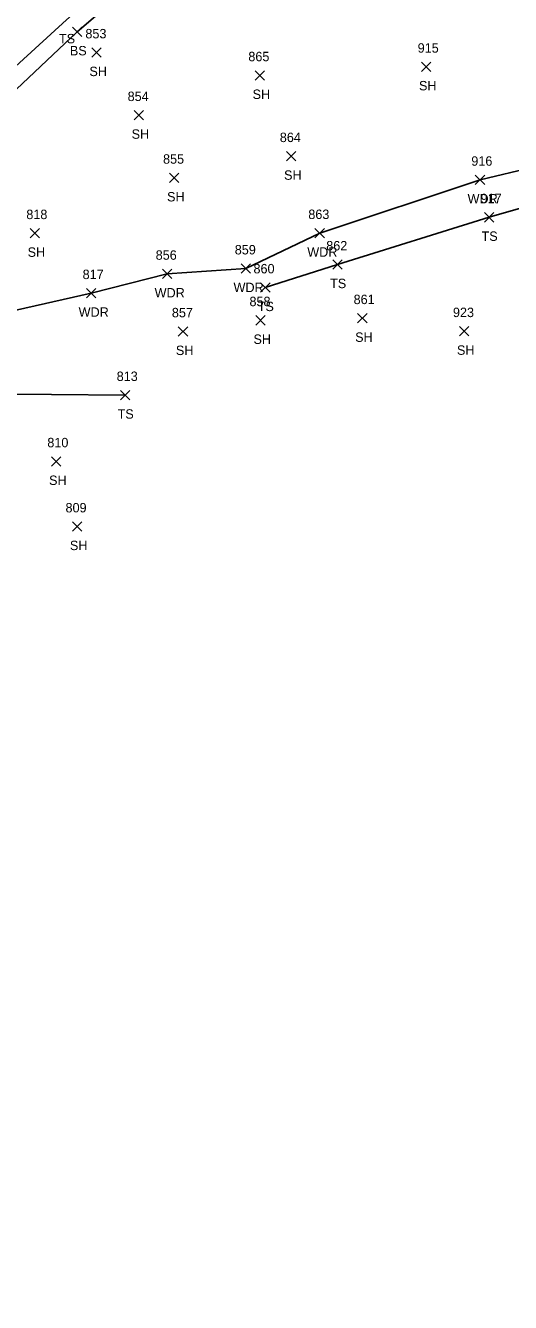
# Model space of a CAD drawing. Extents: x 1586965 to 1590952, y 716317 to 720029.
# Drawn here: x 1587304.9 to 1587407.7, y 719388.4 to 719659.2 of the extents above; entities that cross this region are included whole.
import ezdxf

# ---------------------------------------------------------------- set-up
doc = ezdxf.new("R2010")
doc.units = 0
for name, color, linetype in [('L_A', 7, 'Continuous'), ('L_I', 7, 'Continuous'), ('L_TIC', 7, 'Continuous'), ('LAWA', 7, 'Continuous'), ('LELB', 7, 'Continuous')]:
    doc.layers.add(name, color=color, linetype=linetype)

msp = doc.modelspace()

# ---------------------------------------------------------------- linework, layer by layer
at = {"layer": 'L_TIC'}
for points in [[(1587314.89, 719656.91), (1587316.89, 719658.91)], [(1587316.89, 719656.91), (1587314.89, 719658.91)], [(1587318.98, 719652.52), (1587320.98, 719654.52)], [(1587320.98, 719652.52), (1587318.98, 719654.52)], [(1587353.57, 719647.67), (1587355.57, 719649.67)], [(1587355.57, 719647.67), (1587353.57, 719649.67)], [(1587388.85, 719649.49), (1587390.85, 719651.49)], [(1587390.85, 719649.49), (1587388.85, 719651.49)], [(1587327.93, 719639.23), (1587329.93, 719641.23)], [(1587329.93, 719639.23), (1587327.93, 719641.23)], [(1587360.24, 719630.53), (1587362.24, 719632.53)], [(1587362.24, 719630.53), (1587360.24, 719632.53)], [(1587335.45, 719625.94), (1587337.45, 719627.94)], [(1587337.45, 719625.94), (1587335.45, 719627.94)], [(1587400.27, 719625.51), (1587402.27, 719627.51)], [(1587402.27, 719625.51), (1587400.27, 719627.51)], [(1587402.18, 719617.57), (1587404.18, 719619.57)], [(1587404.18, 719617.57), (1587402.18, 719619.57)], [(1587305.9, 719614.19), (1587307.9, 719616.19)], [(1587307.9, 719614.19), (1587305.9, 719616.19)], [(1587366.28, 719614.21), (1587368.28, 719616.21)], [(1587368.28, 719614.21), (1587366.28, 719616.21)], [(1587350.65, 719606.7), (1587352.65, 719608.7)], [(1587352.65, 719606.7), (1587350.65, 719608.7)], [(1587370.08, 719607.55), (1587372.08, 719609.55)], [(1587372.08, 719607.55), (1587370.08, 719609.55)], [(1587333.94, 719605.57), (1587335.94, 719607.57)], [(1587335.94, 719605.57), (1587333.94, 719607.57)], [(1587317.82, 719601.47), (1587319.82, 719603.47)], [(1587319.82, 719601.47), (1587317.82, 719603.47)], [(1587354.75, 719602.68), (1587356.75, 719604.68)], [(1587356.75, 719602.68), (1587354.75, 719604.68)], [(1587375.32, 719596.16), (1587377.32, 719598.16)], [(1587377.32, 719596.16), (1587375.32, 719598.16)], [(1587337.31, 719593.36), (1587339.31, 719595.36)], [(1587339.31, 719593.36), (1587337.31, 719595.36)], [(1587353.76, 719595.72), (1587355.76, 719597.72)], [(1587355.76, 719595.72), (1587353.76, 719597.72)], [(1587396.9, 719593.41), (1587398.9, 719595.41)], [(1587398.9, 719593.41), (1587396.9, 719595.41)], [(1587325.04, 719579.86), (1587327.04, 719581.86)], [(1587327.04, 719579.86), (1587325.04, 719581.86)], [(1587310.44, 719565.8), (1587312.44, 719567.8)], [(1587312.44, 719565.8), (1587310.44, 719567.8)], [(1587314.86, 719551.99), (1587316.86, 719553.99)], [(1587316.86, 719551.99), (1587314.86, 719553.99)]]:
    msp.add_lwpolyline(points, dxfattribs=at)
at = {"layer": 'LAWA'}
msp.add_lwpolyline([(1587171.91, 719364.5), (1587185.92, 719394.62), (1587194.51, 719437.33), (1587204.69, 719465.5), (1587209.04, 719470.1), (1587216.07, 719486.45), (1587218.68, 719500.05), (1587226.66, 719522.84), (1587234.63, 719543.06), (1587243.18, 719549.48), (1587251, 719567.85), (1587260.43, 719579.32), (1587269.2, 719595.73), (1587274.23, 719603.67), (1587301.03, 719598.43), (1587318.82, 719602.47), (1587334.94, 719606.57), (1587351.65, 719607.7), (1587367.28, 719615.21), (1587401.27, 719626.51), (1587435.01, 719634.6)], dxfattribs=at)
at = {"layer": 'LELB'}
for points in [[(1587111.95, 719287.48), (1587133.61, 719303.61), (1587148.92, 719323.42), (1587167.88, 719366.46), (1587179.01, 719397.6), (1587173.15, 719399.12), (1587186.97, 719441.05), (1587200.36, 719482.43), (1587215.71, 719524.53), (1587222.82, 719545.46), (1587239.38, 719574.3), (1587247.92, 719589.42), (1587267.49, 719614.08), (1587286.95, 719636.16), (1587313.61, 719660.46), (1587335.34, 719679.69), (1587361.68, 719697.91), (1587398.24, 719722.21), (1587438.94, 719742.74)], [(1587111.95, 719287.48), (1587133.61, 719303.61), (1587148.92, 719323.42), (1587167.88, 719366.46), (1587179.01, 719397.6), (1587173.15, 719399.12), (1587186.97, 719441.05), (1587200.36, 719482.43), (1587215.71, 719524.53), (1587222.82, 719545.46), (1587239.38, 719574.3), (1587247.92, 719589.42), (1587267.49, 719614.08), (1587286.95, 719636.16), (1587313.61, 719660.46), (1587335.34, 719679.69), (1587361.68, 719697.91), (1587398.24, 719722.21), (1587438.94, 719742.74)], [(1587178.28, 719402.93), (1587189.21, 719440.25), (1587198.32, 719468.09), (1587203.86, 719481.06), (1587218.12, 719523.56), (1587224.35, 719543.95), (1587223.87, 719544.83), (1587224.18, 719545.53), (1587225.1, 719545.69), (1587240.99, 719573.37), (1587249.54, 719588.04), (1587270.51, 719611.5), (1587289.99, 719633.55), (1587315.89, 719657.91), (1587337.85, 719676.76), (1587363.47, 719694.64), (1587400.93, 719718.94), (1587441.36, 719738.52)], [(1587178.28, 719402.93), (1587189.21, 719440.25), (1587198.32, 719468.09), (1587203.86, 719481.06), (1587218.12, 719523.56), (1587224.35, 719543.95), (1587223.87, 719544.83), (1587224.18, 719545.53), (1587225.1, 719545.69), (1587240.99, 719573.37), (1587249.54, 719588.04), (1587270.51, 719611.5), (1587289.99, 719633.55), (1587315.89, 719657.91), (1587337.85, 719676.76), (1587363.47, 719694.64), (1587400.93, 719718.94), (1587441.36, 719738.52)], [(1587355.75, 719603.68), (1587371.08, 719608.55), (1587403.18, 719618.57), (1587428.15, 719625.76), (1587443.13, 719623.92), (1587426.64, 719618.54), (1587410.99, 719610.06), (1587414.34, 719601.01)], [(1587355.75, 719603.68), (1587371.08, 719608.55), (1587403.18, 719618.57), (1587428.15, 719625.76), (1587443.13, 719623.92), (1587426.64, 719618.54), (1587410.99, 719610.06), (1587414.34, 719601.01)], [(1587260.43, 719579.32), (1587294.72, 719581.16), (1587326.04, 719580.86)], [(1587260.43, 719579.32), (1587294.72, 719581.16), (1587326.04, 719580.86)]]:
    msp.add_lwpolyline(points, dxfattribs=at)

# ---------------------------------------------------------------- texts
at = {"layer": 'L_A'}
for s, p in [('TS', (1587312.02, 719655.46)), ('BS', (1587314.33, 719652.91)), ('SH', (1587318.47, 719648.52)), ('SH', (1587388.33, 719645.49)), ('SH', (1587353.06, 719643.67)), ('SH', (1587327.42, 719635.23)), ('SH', (1587359.73, 719626.53)), ('SH', (1587334.93, 719621.94)), ('WDR', (1587398.63, 719621.51)), ('TS', (1587401.59, 719613.57)), ('SH', (1587305.38, 719610.19)), ('WDR', (1587364.65, 719610.21)), ('WDR', (1587332.3, 719601.57)), ('WDR', (1587349.02, 719602.7)), ('TS', (1587369.49, 719603.55)), ('TS', (1587354.16, 719598.68)), ('WDR', (1587316.19, 719597.47)), ('SH', (1587353.25, 719591.72)), ('SH', (1587374.8, 719592.16)), ('SH', (1587336.8, 719589.36)), ('SH', (1587396.38, 719589.41)), ('TS', (1587324.45, 719575.86)), ('SH', (1587309.92, 719561.8)), ('SH', (1587314.34, 719547.99))]:
    msp.add_text(s, height=2, dxfattribs=at).set_placement(p)
at = {"layer": 'L_I'}
for s, p in [('853', (1587317.62, 719656.52)), ('915', (1587388.05, 719653.49)), ('865', (1587352.16, 719651.67)), ('854', (1587326.57, 719643.23)), ('864', (1587358.83, 719634.53)), ('855', (1587334.08, 719629.94)), ('916', (1587399.42, 719629.51)), ('917', (1587401.39, 719621.57)), ('818', (1587305.1, 719618.19)), ('863', (1587364.87, 719618.21)), ('856', (1587332.52, 719609.57)), ('859', (1587349.28, 719610.7)), ('862', (1587368.67, 719611.55)), ('860', (1587353.25, 719606.68)), ('817', (1587317.03, 719605.47)), ('858', (1587352.4, 719599.72)), ('861', (1587374.47, 719600.16)), ('857', (1587335.95, 719597.36)), ('923', (1587395.53, 719597.41)), ('813', (1587324.25, 719583.86)), ('810', (1587309.55, 719569.8)), ('809', (1587313.41, 719555.99))]:
    msp.add_text(s, height=2, dxfattribs=at).set_placement(p)

doc.saveas('drawing.dxf')
